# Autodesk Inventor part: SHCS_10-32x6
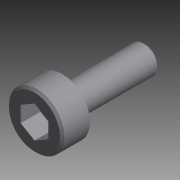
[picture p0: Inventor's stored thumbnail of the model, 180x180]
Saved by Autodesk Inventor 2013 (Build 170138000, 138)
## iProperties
Shininess: 0.0
Length Units: 11272
Angle Units: 11279
Time Units: 11290
Mass Units: 11283
Length Display Precision: 2
Angle Display Precision: 1
Compacted: True
Created: 1999-05
Part Number: SHCS_10-32x6
Document SubType Name: Modeling
Designer: Administrator
Density: 7.84 g/cm^3
Material: Steel, High Strength Low Alloy
Mass: 1.21578 g
Surface Area: 2.42207 cm^2
Volume: 0.155074 cm^3
Density: 0.0
Volumn: 0.0
Area: 0.0
PropertySet Name: Model Information
Control State: 0
Master: False
Checked Out: False
Author: Administrator
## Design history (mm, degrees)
node "y-z Plane"
  node "x-z Plane"
  node "x-y Plane"
node "Extrusion1" dims "d1" = 3.175, "d2" = 0
  sketch "Sketch1"
    geometry: C1 r 3.175 at (0, 0); 1 further point
    constraints: 1 centre point, 1 coincident
    dimensions: "d0" = 6.35 diameter of C1
node "Chamfer1" dims "d3" = 0.254, "d4" = 0.254, "d18" = 45 deg
node "Extrusion3" dims "d10" = 9.525, "d11" = 0
  sketch "Sketch3"
    geometry: C1 r 3.175 at (0, 0) reference; C2 r 1.587 at (0, 0)
    constraints: 1 centre point
    dimensions: "d9" = 3.175 diameter of C2
node "Chamfer2" dims "d12" = 0.254, "d13" = 0.254, "d19" = 45 deg
node "Extrusion4" dims "d16" = 2.286, "d17" = 0
  sketch "Sketch4"
    geometry: L1 (0, 4.445)-(0, -4.445) reference; L2 (-4.445, 0)-(4.445, 0) reference; L3 (0, 1.833)-(-1.588, 0.917); L4 (-1.588, 0.917)-(-1.588, -0.917); L5 (-1.588, -0.917)-(0, -1.833); L6 (0, -1.833)-(1.588, -0.917); L7 (1.588, -0.917)-(1.588, 0.917); L8 (1.588, 0.917)-(0, 1.833); C1 r 2.921 at (0, 0) reference; A1 r 1.833 centre (0, 0) between (0, 1.833) and (-1.588, 0.917)
    constraints: 12 end point, 6 point on circle, 3 parallel, 2 point on line, 1 centre point, 1 coincident, 1 perpendicular
    dimensions: "d14" = 120 deg angle of L8 L3; "d15" = 3.175 distance between parallel lines of L6 L3
body "Solid1"
